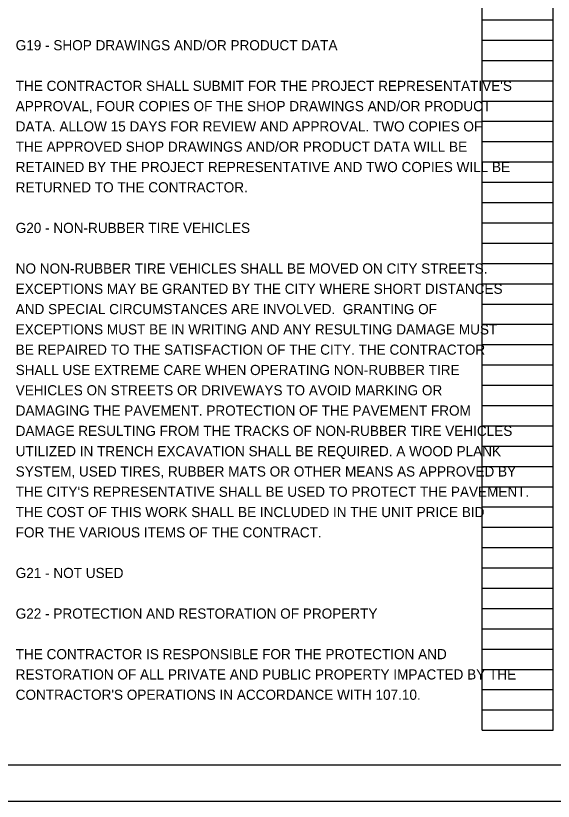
# Model space of a CAD drawing. Extents: x 0 to 37.1, y 0 to 22.
# Drawn here: x 17.24 to 24.66, y 0 to 10.84 of the extents above; entities that cross this region are included whole.
import ezdxf

# ---------------------------------------------------------------- set-up
doc = ezdxf.new("R2010")
doc.units = 0
for name, color, linetype in [('SH_Border', 7, 'Continuous'), ('SH_Cut_Line', 7, 'Continuous'), ('SH_Data', 7, 'Continuous'), ('SH_Text', 7, 'Continuous')]:
    doc.layers.add(name, color=color, linetype=linetype)

msp = doc.modelspace()

# ---------------------------------------------------------------- linework, layer by layer
at = {"layer": 'SH_Border'}
msp.add_lwpolyline([(1.5, 21.5), (33.5, 21.5), (33.5, 0.5), (1.5, 0.5)], close=True, dxfattribs=at)
at = {"layer": 'SH_Cut_Line'}
msp.add_lwpolyline([(0, 0), (34, 0), (34, 22), (0, 22)], close=True, dxfattribs=at)
at = {"layer": 'SH_Data'}
for p, q in [((23.68, 0.98), (23.68, 21.14)), ((24.66, 0.98), (24.66, 21.14)), ((23.68, 10.78), (24.66, 10.78)), ((23.68, 10.5), (24.66, 10.5)), ((23.68, 10.22), (24.66, 10.22)), ((23.68, 9.94), (24.66, 9.94)), ((23.68, 9.66), (24.66, 9.66)), ((23.68, 9.38), (24.66, 9.38)), ((23.68, 9.1), (24.66, 9.1)), ((23.68, 8.82), (24.66, 8.82)), ((23.68, 8.54), (24.66, 8.54)), ((23.68, 8.26), (24.66, 8.26)), ((23.68, 7.98), (24.66, 7.98)), ((23.68, 7.7), (24.66, 7.7)), ((23.68, 7.42), (24.66, 7.42)), ((23.68, 7.14), (24.66, 7.14)), ((23.68, 6.86), (24.66, 6.86)), ((23.68, 6.58), (24.66, 6.58)), ((23.68, 6.3), (24.66, 6.3)), ((23.68, 6.02), (24.66, 6.02)), ((23.68, 5.74), (24.66, 5.74)), ((23.68, 5.46), (24.66, 5.46)), ((23.68, 5.18), (24.66, 5.18)), ((23.68, 4.9), (24.66, 4.9)), ((23.68, 4.62), (24.66, 4.62)), ((23.68, 4.34), (24.66, 4.34)), ((23.68, 4.06), (24.66, 4.06)), ((23.68, 3.78), (24.66, 3.78)), ((23.68, 3.5), (24.66, 3.5)), ((23.68, 3.22), (24.66, 3.22)), ((23.68, 2.94), (24.66, 2.94)), ((23.68, 2.66), (24.66, 2.66)), ((23.68, 2.38), (24.66, 2.38)), ((23.68, 2.1), (24.66, 2.1)), ((23.68, 1.82), (24.66, 1.82)), ((23.68, 1.54), (24.66, 1.54)), ((23.68, 1.26), (24.66, 1.26)), ((23.68, 0.98), (24.66, 0.98))]:
    msp.add_line(p, q, dxfattribs=at)

# ---------------------------------------------------------------- texts
at = {"layer": 'SH_Text'}
for s, p in [('G19 - SHOP DRAWINGS AND/OR PRODUCT DATA', (17.24, 10.36)), ("THE CONTRACTOR SHALL SUBMIT FOR THE PROJECT REPRESENTATIVE'S ", (17.24, 9.8)), ('APPROVAL, FOUR COPIES OF THE SHOP DRAWINGS AND/OR PRODUCT ', (17.24, 9.52)), ('DATA. ALLOW 15 DAYS FOR REVIEW AND APPROVAL. TWO COPIES OF ', (17.24, 9.24)), ('THE APPROVED SHOP DRAWINGS AND/OR PRODUCT DATA WILL BE ', (17.24, 8.96)), ('RETAINED BY THE PROJECT REPRESENTATIVE AND TWO COPIES WILL BE ', (17.24, 8.68)), ('RETURNED TO THE CONTRACTOR. ', (17.24, 8.4)), ('G20 - NON-RUBBER TIRE VEHICLES', (17.24, 7.84)), ('NO NON-RUBBER TIRE VEHICLES SHALL BE MOVED ON CITY STREETS. ', (17.24, 7.28)), ('EXCEPTIONS MAY BE GRANTED BY THE CITY WHERE SHORT DISTANCES ', (17.24, 7)), ('AND SPECIAL CIRCUMSTANCES ARE INVOLVED.  GRANTING OF ', (17.24, 6.72)), ('EXCEPTIONS MUST BE IN WRITING AND ANY RESULTING DAMAGE MUST ', (17.24, 6.44)), ('BE REPAIRED TO THE SATISFACTION OF THE CITY. THE CONTRACTOR ', (17.24, 6.16)), ('SHALL USE EXTREME CARE WHEN OPERATING NON-RUBBER TIRE ', (17.24, 5.88)), ('VEHICLES ON STREETS OR DRIVEWAYS TO AVOID MARKING OR ', (17.24, 5.6)), ('DAMAGING THE PAVEMENT. PROTECTION OF THE PAVEMENT FROM ', (17.24, 5.32)), ('DAMAGE RESULTING FROM THE TRACKS OF NON-RUBBER TIRE VEHICLES ', (17.24, 5.04)), ('UTILIZED IN TRENCH EXCAVATION SHALL BE REQUIRED. A WOOD PLANK ', (17.24, 4.76)), ('SYSTEM, USED TIRES, RUBBER MATS OR OTHER MEANS AS APPROVED BY ', (17.24, 4.48)), ("THE CITY'S REPRESENTATIVE SHALL BE USED TO PROTECT THE PAVEMENT.  ", (17.24, 4.2)), ('THE COST OF THIS WORK SHALL BE INCLUDED IN THE UNIT PRICE BID ', (17.24, 3.92)), ('FOR THE VARIOUS ITEMS OF THE CONTRACT.  ', (17.24, 3.64)), ('G21 - NOT USED', (17.24, 3.08)), ('G22 - PROTECTION AND RESTORATION OF PROPERTY', (17.24, 2.52)), ('THE CONTRACTOR IS RESPONSIBLE FOR THE PROTECTION AND ', (17.24, 1.96)), ('RESTORATION OF ALL PRIVATE AND PUBLIC PROPERTY IMPACTED BY THE ', (17.24, 1.68)), ("CONTRACTOR'S OPERATIONS IN ACCORDANCE WITH 107.10.", (17.24, 1.4))]:
    msp.add_text(s, height=0.14, dxfattribs=at).set_placement(p)

doc.saveas('drawing.dxf')
